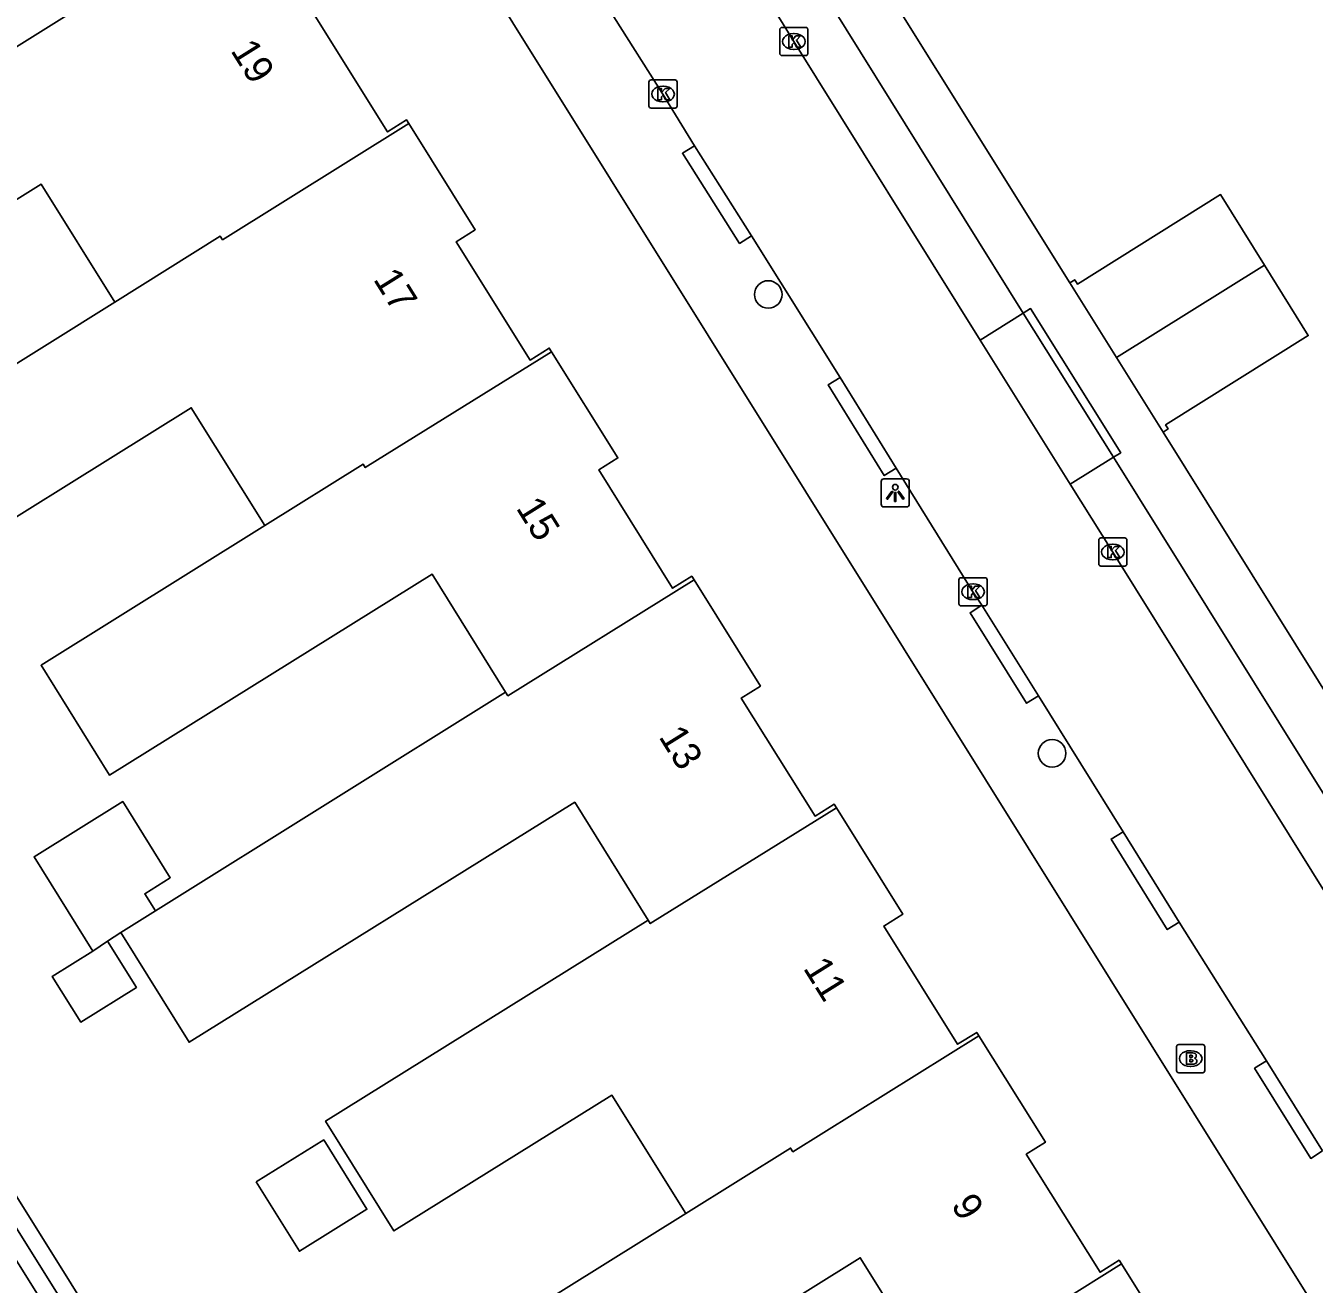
# Model space of a CAD drawing. Extents: x 158838 to 160074, y 386376 to 387776.
# Drawn here: x 159122.08 to 159167.82, y 386876.1 to 386920.78 of the extents above; entities that cross this region are included whole.
import ezdxf

# ---------------------------------------------------------------- set-up
doc = ezdxf.new("R2010")
doc.units = 0
for name, color, linetype in [('IMGEO_Boom', 7, 'Continuous'), ('IMGEO_Brandkraan', 7, 'Continuous'), ('IMGEO_Groenvoorziening', 7, 'Continuous'), ('IMGEO_Kolk', 7, 'Continuous'), ('IMGEO_Lichtpunt', 7, 'Continuous'), ('IMGEO_Muur', 7, 'Continuous'), ('IMGEO_Pand', 7, 'Continuous'), ('IMGEO_Pand_nummerreeks', 7, 'Continuous'), ('IMGEO_Parkeervlak_open', 7, 'Continuous'), ('IMGEO_Rijbaan_lokaal_open', 7, 'Continuous'), ('IMGEO_Voetpad_open', 7, 'Continuous')]:
    doc.layers.add(name, color=color, linetype=linetype)

msp = doc.modelspace()

# ---------------------------------------------------------------- linework, layer by layer
at = {"layer": 'IMGEO_Boom'}
for centre in [(159148.436, 386911.238), (159158.511, 386894.949)]:
    msp.add_circle(centre, 0.489, dxfattribs=at)
at = {"layer": 'IMGEO_Brandkraan'}
for p, q in [((159162.93, 386883.686), (159162.93, 386884.538)), ((159163.005, 386884.612), (159163.857, 386884.612)), ((159163.931, 386884.538), (159163.931, 386883.686)), ((159163.418, 386884.392), (159163.443, 386884.392)), ((159163.857, 386883.612), (159163.005, 386883.612)), ((159163.441, 386883.832), (159163.416, 386883.832))]:
    msp.add_line(p, q, dxfattribs=at)
for points in [[(159162.93, 386883.686), (159162.93, 386884.538)], [(159163.005, 386884.612), (159163.857, 386884.612)], [(159163.931, 386884.538), (159163.931, 386883.686)], [(159163.278, 386884.312), (159163.278, 386883.912), (159163.491, 386883.912)], [(159163.509, 386884.312), (159163.278, 386884.312)], [(159163.457, 386884.231), (159163.403, 386884.231), (159163.403, 386884.155)], [(159163.403, 386884.155), (159163.456, 386884.155)], [(159163.465, 386884.079), (159163.403, 386884.079), (159163.403, 386883.998)], [(159163.857, 386883.612), (159163.005, 386883.612)], [(159163.403, 386883.998), (159163.465, 386883.998)]]:
    msp.add_lwpolyline(points, dxfattribs=at)
for centre, radius, start, end in [((159163.007, 386884.536), 0.0765, 91.552, 178.448), ((159163.007, 386884.536), 0.0765, 91.552, 178.448), ((159163.855, 386884.536), 0.0765, 1.552, 88.448), ((159163.855, 386884.536), 0.0765, 1.552, 88.448), ((159163.458, 386884.193), 0.0379, 267.8285, 90.9355), ((159163.466, 386884.038), 0.0404, 269.8759, 90.5077), ((159163.513, 386884.167), 0.145, 59.4692, 91.5367), ((159163.538, 386884.214), 0.0922, 285.5137, 58.1501), ((159163.543, 386884.022), 0.105, 301.3115, 78.989), ((159163.007, 386883.688), 0.0765, 181.552, 268.448), ((159163.007, 386883.688), 0.0765, 181.552, 268.448), ((159163.497, 386884.163), 0.251, 268.6676, 293.5347), ((159163.855, 386883.688), 0.0765, 271.552, 358.448), ((159163.855, 386883.688), 0.0765, 271.552, 358.448)]:
    msp.add_arc(centre, radius, start, end, dxfattribs=at)
for centre, major_axis, ratio, start_param, end_param in [((159163.417, 386884.112), (-0.387, 0.002), 0.722429, 4.712389, 7.853982), ((159163.442, 386884.112), (-0.39, 0.002), 0.717154, 1.570796, 4.712389)]:
    msp.add_ellipse(centre, major_axis=major_axis, ratio=ratio, start_param=start_param, end_param=end_param, dxfattribs=at)
at = {"layer": 'IMGEO_Groenvoorziening'}
for points in [[(159153.383, 386826.367), (159102.052, 386908.422), (159101.832, 386908.935), (159101.604, 386909.612), (159101.437, 386910.307), (159101.332, 386911.014), (159101.291, 386911.728), (159101.315, 386912.442), (159101.402, 386913.152), (159101.551, 386913.851), (159101.763, 386914.534), (159102.035, 386915.195), (159102.365, 386915.829)], [(159102.915, 386915.575), (159102.608, 386914.992), (159102.355, 386914.384), (159102.156, 386913.756), (159102.015, 386913.113), (159101.932, 386912.46), (159101.907, 386911.802), (159101.941, 386911.144), (159102.034, 386910.492), (159102.185, 386909.851), (159102.393, 386909.226), (159102.615, 386908.705), (159154.046, 386826.389)], [(159154.526, 386826.749), (159103.157, 386908.962)]]:
    msp.add_lwpolyline(points, dxfattribs=at)
at = {"layer": 'IMGEO_Kolk'}
for p, q in [((159148.843, 386919.792), (159148.843, 386920.644)), ((159148.918, 386920.718), (159149.77, 386920.718)), ((159149.844, 386920.644), (159149.844, 386919.792)), ((159149.331, 386920.498), (159149.356, 386920.498)), ((159149.77, 386919.718), (159148.918, 386919.718)), ((159149.354, 386919.938), (159149.329, 386919.938)), ((159144.274, 386918.853), (159145.126, 386918.853)), ((159144.199, 386917.927), (159144.199, 386918.779)), ((159144.687, 386918.633), (159144.712, 386918.633)), ((159145.2, 386918.779), (159145.2, 386917.927)), ((159144.71, 386918.073), (159144.685, 386918.073)), ((159145.126, 386917.853), (159144.274, 386917.853)), ((159160.165, 386901.669), (159160.165, 386902.521)), ((159160.24, 386902.595), (159161.092, 386902.595)), ((159160.653, 386902.375), (159160.678, 386902.375)), ((159161.166, 386902.521), (159161.166, 386901.669)), ((159161.092, 386901.595), (159160.24, 386901.595)), ((159160.676, 386901.815), (159160.651, 386901.815)), ((159155.204, 386900.258), (159155.204, 386901.11)), ((159155.279, 386901.184), (159156.131, 386901.184)), ((159155.692, 386900.964), (159155.717, 386900.964)), ((159156.205, 386901.11), (159156.205, 386900.258)), ((159156.131, 386900.184), (159155.279, 386900.184)), ((159155.715, 386900.404), (159155.69, 386900.404))]:
    msp.add_line(p, q, dxfattribs=at)
for points in [[(159148.843, 386919.792), (159148.843, 386920.644)], [(159148.918, 386920.718), (159149.77, 386920.718)], [(159149.844, 386920.644), (159149.844, 386919.792)], [(159149.164, 386920.418), (159149.287, 386920.418), (159149.287, 386920.267), (159149.417, 386920.418), (159149.581, 386920.418), (159149.435, 386920.267), (159149.588, 386920.018), (159149.436, 386920.018), (159149.351, 386920.182), (159149.287, 386920.115), (159149.287, 386920.018), (159149.164, 386920.018), (159149.164, 386920.418)], [(159149.77, 386919.718), (159148.918, 386919.718)], [(159144.274, 386918.853), (159145.126, 386918.853)], [(159144.199, 386917.927), (159144.199, 386918.779)], [(159144.52, 386918.553), (159144.643, 386918.553), (159144.643, 386918.402), (159144.773, 386918.553), (159144.937, 386918.553), (159144.791, 386918.402), (159144.944, 386918.153), (159144.792, 386918.153), (159144.707, 386918.317), (159144.643, 386918.25), (159144.643, 386918.153), (159144.52, 386918.153), (159144.52, 386918.553)], [(159145.2, 386918.779), (159145.2, 386917.927)], [(159145.126, 386917.853), (159144.274, 386917.853)], [(159160.165, 386901.669), (159160.165, 386902.521)], [(159160.24, 386902.595), (159161.092, 386902.595)], [(159161.166, 386902.521), (159161.166, 386901.669)], [(159160.486, 386902.295), (159160.609, 386902.295), (159160.609, 386902.144), (159160.739, 386902.295), (159160.903, 386902.295), (159160.757, 386902.144), (159160.91, 386901.895), (159160.758, 386901.895), (159160.673, 386902.059), (159160.609, 386901.992), (159160.609, 386901.895), (159160.486, 386901.895), (159160.486, 386902.295)], [(159161.092, 386901.595), (159160.24, 386901.595)], [(159155.204, 386900.258), (159155.204, 386901.11)], [(159155.279, 386901.184), (159156.131, 386901.184)], [(159156.205, 386901.11), (159156.205, 386900.258)], [(159155.525, 386900.884), (159155.648, 386900.884), (159155.648, 386900.733), (159155.778, 386900.884), (159155.942, 386900.884), (159155.796, 386900.733), (159155.949, 386900.484), (159155.797, 386900.484), (159155.712, 386900.648), (159155.648, 386900.581), (159155.648, 386900.484), (159155.525, 386900.484), (159155.525, 386900.884)], [(159156.131, 386900.184), (159155.279, 386900.184)]]:
    msp.add_lwpolyline(points, dxfattribs=at)
for centre, start, end in [((159148.92, 386920.642), 91.552, 178.448), ((159148.92, 386920.642), 91.552, 178.448), ((159149.768, 386920.642), 1.552, 88.448), ((159149.768, 386920.642), 1.552, 88.448), ((159148.92, 386919.794), 181.552, 268.448), ((159148.92, 386919.794), 181.552, 268.448), ((159149.768, 386919.794), 271.552, 358.448), ((159149.768, 386919.794), 271.552, 358.448), ((159144.276, 386918.777), 91.552, 178.448), ((159144.276, 386918.777), 91.552, 178.448), ((159145.124, 386918.777), 1.552, 88.448), ((159145.124, 386918.777), 1.552, 88.448), ((159144.276, 386917.929), 181.552, 268.448), ((159144.276, 386917.929), 181.552, 268.448), ((159145.124, 386917.929), 271.552, 358.448), ((159145.124, 386917.929), 271.552, 358.448), ((159160.242, 386902.519), 91.552, 178.448), ((159160.242, 386902.519), 91.552, 178.448), ((159161.09, 386902.519), 1.552, 88.448), ((159161.09, 386902.519), 1.552, 88.448), ((159160.242, 386901.671), 181.552, 268.448), ((159160.242, 386901.671), 181.552, 268.448), ((159161.09, 386901.671), 271.552, 358.448), ((159161.09, 386901.671), 271.552, 358.448), ((159155.281, 386901.108), 91.552, 178.448), ((159155.281, 386901.108), 91.552, 178.448), ((159156.129, 386901.108), 1.552, 88.448), ((159156.129, 386901.108), 1.552, 88.448), ((159155.281, 386900.26), 181.552, 268.448), ((159155.281, 386900.26), 181.552, 268.448), ((159156.129, 386900.26), 271.552, 358.448), ((159156.129, 386900.26), 271.552, 358.448)]:
    msp.add_arc(centre, 0.0765, start, end, dxfattribs=at)
for centre, major_axis, ratio, start_param, end_param in [((159149.33, 386920.218), (-0.387, 0.002), 0.722429, 4.712389, 7.853982), ((159149.355, 386920.218), (-0.39, 0.002), 0.717154, 1.570796, 4.712389), ((159144.686, 386918.353), (-0.387, 0.002), 0.722429, 4.712389, 7.853982), ((159144.711, 386918.353), (-0.39, 0.002), 0.717154, 1.570796, 4.712389), ((159160.652, 386902.095), (-0.387, 0.002), 0.722429, 4.712389, 7.853982), ((159160.677, 386902.095), (-0.39, 0.002), 0.717154, 1.570796, 4.712389), ((159155.691, 386900.684), (-0.387, 0.002), 0.722429, 4.712389, 7.853982), ((159155.716, 386900.684), (-0.39, 0.002), 0.717154, 1.570796, 4.712389)]:
    msp.add_ellipse(centre, major_axis=major_axis, ratio=ratio, start_param=start_param, end_param=end_param, dxfattribs=at)
at = {"layer": 'IMGEO_Lichtpunt'}
for p, q in [((159153.347, 386904.692), (159152.539, 386904.692)), ((159153.347, 386904.692), (159152.539, 386904.692)), ((159152.445, 386904.597), (159152.445, 386903.79)), ((159152.445, 386904.597), (159152.445, 386903.79)), ((159153.441, 386903.79), (159153.441, 386904.597)), ((159153.441, 386903.79), (159153.441, 386904.597)), ((159152.539, 386903.696), (159153.347, 386903.696)), ((159152.539, 386903.696), (159153.347, 386903.696))]:
    msp.add_line(p, q, dxfattribs=at)
for points in [[(159152.819, 386904.261), (159152.858, 386904.233), (159152.67, 386903.971), (159152.632, 386903.998), (159152.819, 386904.261)], [(159152.921, 386904.213), (159152.968, 386904.213), (159152.968, 386903.891), (159152.921, 386903.891), (159152.921, 386904.213)], [(159153.031, 386904.233), (159153.069, 386904.26), (159153.256, 386903.998), (159153.217, 386903.97), (159153.031, 386904.233)]]:
    msp.add_lwpolyline(points, dxfattribs=at)
msp.add_circle((159152.944, 386904.395), 0.0994, dxfattribs=at)
for centre, start, end in [((159152.539, 386904.597), 90, 180), ((159152.539, 386904.597), 90, 180), ((159153.347, 386904.597), 0, 90), ((159153.347, 386904.597), 0, 90), ((159152.539, 386903.79), 180, 270), ((159152.539, 386903.79), 180, 270), ((159153.347, 386903.79), 270, 0), ((159153.347, 386903.79), 270, 360)]:
    msp.add_arc(centre, 0.0946, start, end, dxfattribs=at)
at = {"layer": 'IMGEO_Muur'}
for points in [[(159149.74, 386926.686), (159159.144, 386911.655)], [(159162.452, 386906.354), (159169.519, 386895.024)]]:
    msp.add_lwpolyline(points, dxfattribs=at)
at = {"layer": 'IMGEO_Pand'}
for points in [[(159135.679, 386917.307), (159135.599, 386917.434), (159134.92, 386917.01), (159132.297, 386921.208), (159132.976, 386921.632), (159130.533, 386925.542)], [(159123.926, 386921.395), (159112.501, 386914.25), (159114.935, 386910.349), (159122.629, 386915.15), (159125.239, 386910.966)], [(159125.239, 386910.966), (159128.984, 386913.306), (159129.063, 386913.179), (159135.679, 386917.307)], [(159140.738, 386909.207), (159140.659, 386909.334), (159139.981, 386908.911), (159137.358, 386913.109), (159138.036, 386913.533), (159135.679, 386917.307)], [(159159.144, 386911.655), (159159.314, 386911.761), (159159.41, 386911.608), (159164.491, 386914.784), (159166.046, 386912.282)], [(159166.046, 386912.282), (159160.798, 386909.004)], [(159166.046, 386912.282), (159167.601, 386909.78), (159162.54, 386906.61), (159162.63, 386906.466), (159162.452, 386906.354)], [(159160.798, 386909.004), (159159.144, 386911.655)], [(159125.239, 386910.966), (159115.339, 386904.78), (159117.771, 386900.875), (159127.954, 386907.217), (159130.562, 386903.037)], [(159140.738, 386909.207), (159134.13, 386905.092), (159134.051, 386905.219), (159130.562, 386903.037)], [(159145.8, 386901.108), (159145.72, 386901.235), (159145.041, 386900.811), (159142.418, 386905.009), (159143.097, 386905.433), (159140.738, 386909.207)], [(159162.452, 386906.354), (159160.798, 386909.004)], [(159130.562, 386903.037), (159122.623, 386898.073), (159125.05, 386894.177), (159136.501, 386901.311), (159139.113, 386897.119)], [(159145.8, 386901.108), (159139.192, 386896.992), (159139.113, 386897.119)], [(159150.855, 386893.016), (159150.775, 386893.144), (159150.097, 386892.72), (159147.479, 386896.91), (159148.157, 386897.334), (159145.8, 386901.108)], [(159139.113, 386897.119), (159126.681, 386889.356)], [(159126.681, 386889.356), (159126.3, 386889.967), (159127.208, 386890.532), (159125.523, 386893.238), (159122.373, 386891.275), (159124.458, 386887.927)], [(159125.452, 386888.588), (159127.877, 386884.692), (159141.564, 386893.214), (159144.169, 386889.03)], [(159144.169, 386889.03), (159144.248, 386888.903), (159150.855, 386893.016)], [(159155.915, 386884.917), (159155.836, 386885.044), (159155.157, 386884.621), (159152.534, 386888.819), (159153.213, 386889.243), (159150.855, 386893.016)], [(159125.452, 386888.588), (159126.681, 386889.356)], [(159144.169, 386889.03), (159132.724, 386881.893), (159135.148, 386877.997), (159142.887, 386882.813), (159145.507, 386878.611)], [(159124.458, 386887.927), (159123.019, 386887.031), (159124.028, 386885.41), (159126.005, 386886.64), (159124.985, 386888.278)], [(159124.985, 386888.278), (159124.458, 386887.927)], [(159124.985, 386888.278), (159125.452, 386888.588)], [(159145.507, 386878.611), (159149.229, 386880.933), (159149.308, 386880.806), (159155.915, 386884.917)], [(159160.97, 386876.826), (159160.891, 386876.953), (159160.212, 386876.529), (159157.595, 386880.719), (159158.273, 386881.143), (159155.915, 386884.917)], [(159130.262, 386879.734), (159131.793, 386877.273), (159134.187, 386878.762), (159132.656, 386881.223), (159130.262, 386879.734)], [(159145.507, 386878.611), (159135.531, 386872.387), (159137.969, 386868.478), (159151.702, 386877.045), (159154.326, 386872.839)], [(159160.97, 386876.826), (159154.405, 386872.712), (159154.326, 386872.839)], [(159165.273, 386868.43), (159162.65, 386872.628), (159163.328, 386873.052), (159160.97, 386876.826)]]:
    msp.add_lwpolyline(points, dxfattribs=at)
at = {"layer": 'IMGEO_Parkeervlak_open'}
for points in [[(159155.96, 386909.62), (159157.483, 386910.571)], [(159160.685, 386905.457), (159159.157, 386904.502)]]:
    msp.add_lwpolyline(points, dxfattribs=at)
at = {"layer": 'IMGEO_Rijbaan_lokaal_open'}
for points in [[(159155.96, 386909.62), (159149.339, 386920.217), (159142.148, 386931.913)], [(159142.959, 386921.099), (159144.697, 386918.353), (159145.812, 386916.519)], [(159145.812, 386916.519), (159147.84, 386913.319)], [(159147.84, 386913.319), (159150.982, 386908.288)], [(159159.157, 386904.502), (159155.96, 386909.62)], [(159150.982, 386908.288), (159152.98, 386905.07)], [(159152.98, 386905.07), (159155.702, 386900.684), (159156.02, 386900.204)], [(159173.417, 386881.652), (159172.443, 386883.216), (159160.662, 386902.094), (159159.157, 386904.502)], [(159156.02, 386900.204), (159158.03, 386896.99)], [(159158.03, 386896.99), (159161.031, 386892.166)], [(159161.031, 386892.166), (159163.024, 386888.953)], [(159163.024, 386888.953), (159166.124, 386884.032)], [(159166.124, 386884.032), (159168.115, 386880.832)]]:
    msp.add_lwpolyline(points, dxfattribs=at)
at = {"layer": 'IMGEO_Voetpad_open'}
for points in [[(159159.144, 386911.655), (159149.74, 386926.686), (159145.955, 386932.736), (159145.867, 386932.901), (159145.795, 386933.07), (159145.739, 386933.246), (159145.699, 386933.425), (159145.675, 386933.608), (159145.667, 386933.792), (159145.676, 386933.975), (159145.701, 386934.158), (159145.742, 386934.337), (159145.799, 386934.512), (159145.872, 386934.681), (159145.959, 386934.843), (159146.061, 386934.997), (159146.175, 386935.141), (159146.303, 386935.274), (159146.441, 386935.395), (159146.59, 386935.503)], [(159142.148, 386931.913), (159142.268, 386931.812), (159142.396, 386931.723), (159142.531, 386931.645), (159142.673, 386931.58), (159142.82, 386931.527), (159142.972, 386931.488), (159143.003, 386931.482), (159144.276, 386931.183), (159144.343, 386931.166), (159144.429, 386931.137), (159144.513, 386931.101), (159144.592, 386931.057), (159144.667, 386931.007), (159144.738, 386930.95), (159144.803, 386930.886), (159144.862, 386930.818), (159144.915, 386930.744), (159157.483, 386910.571)], [(159133.211, 386927.185), (159133.374, 386927.263), (159133.544, 386927.327), (159133.719, 386927.374), (159133.897, 386927.406), (159134.078, 386927.422), (159134.259, 386927.421), (159134.439, 386927.405), (159134.618, 386927.372), (159134.792, 386927.324), (159134.962, 386927.26), (159135.125, 386927.181), (159135.281, 386927.088), (159135.427, 386926.982), (159135.564, 386926.863), (159135.689, 386926.732), (159135.802, 386926.59), (159135.902, 386926.439), (159153.24, 386898.677), (159187.007, 386844.595), (159190.588, 386838.84)], [(159147.84, 386913.319), (159147.418, 386913.052), (159145.39, 386916.252), (159145.812, 386916.519)], [(159157.483, 386910.571), (159157.745, 386910.735), (159160.948, 386905.622), (159160.685, 386905.457)], [(159157.483, 386910.571), (159160.685, 386905.457)], [(159152.98, 386905.07), (159152.555, 386904.806), (159150.558, 386908.025), (159150.982, 386908.288)], [(159175.622, 386885.241), (159169.519, 386895.024), (159162.452, 386906.354)], [(159160.685, 386905.457), (159173.235, 386885.356), (159173.242, 386885.346), (159173.286, 386885.27), (159173.324, 386885.191), (159173.354, 386885.108), (159173.377, 386885.024), (159173.392, 386884.937), (159173.399, 386884.85), (159173.398, 386884.762), (159173.39, 386884.675), (159173.374, 386884.589), (159173.122, 386883.15), (159173.099, 386882.956), (159173.093, 386882.762), (159173.105, 386882.567), (159173.134, 386882.374), (159173.18, 386882.185), (159173.243, 386882.001), (159173.322, 386881.822), (159173.417, 386881.652)], [(159158.03, 386896.99), (159157.607, 386896.725), (159155.597, 386899.939), (159156.02, 386900.204)], [(159163.024, 386888.953), (159162.6, 386888.69), (159160.607, 386891.903), (159161.031, 386892.166)], [(159168.115, 386880.832), (159167.691, 386880.568), (159165.7, 386883.768), (159166.124, 386884.032)]]:
    msp.add_lwpolyline(points, dxfattribs=at)

# ---------------------------------------------------------------- texts
at = {"layer": 'IMGEO_Pand_nummerreeks'}
for s, rotation, p in [('19', 301.9601, (159129.328, 386919.898)), ('17', 301.9601, (159134.394, 386911.779)), ('15', 301.9601, (159139.46, 386903.659)), ('13', 301.9594, (159144.526, 386895.539)), ('11', 301.9601, (159149.653, 386887.323)), ('9', 301.9601, (159154.902, 386878.911))]:
    msp.add_text(s, height=1, rotation=rotation, dxfattribs=at).set_placement(p)

doc.saveas('drawing.dxf')
